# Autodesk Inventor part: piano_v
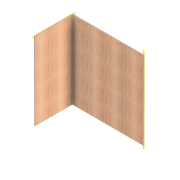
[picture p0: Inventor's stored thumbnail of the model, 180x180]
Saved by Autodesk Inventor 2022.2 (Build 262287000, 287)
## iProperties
Created: 2025-02
Part Number: piano_v
Material: Legno (betulla)
Document SubType Name: Modeling
Designer: 18907419
Density: 0.55 g/cm^3
Appearance: Betulla - Naturale lucidata
Author: 18907419
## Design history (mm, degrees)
node "Piano di lavoro1"
sketch "Schizzo1"
  geometry: L1 (0, -10)-(-20, 10) reference; L2 (-939.693, 10)-(-20, 10) reference; L3 (-939.693, -10)-(-939.693, 10) reference; L4 (-939.693, -10)-(0, -10) reference; L5 (-20, 990)-(0, 1010) reference; L6 (-939.693, 1010)-(0, 1010) reference; L7 (-939.693, 1010)-(-939.693, 990) reference; L8 (-20, 990)-(-939.693, 990) reference; L9 (0, 1010)-(-939.693, 1010); L10 (-939.693, 1010)-(-939.693, -10); L11 (-939.693, -10)-(0, -10); L12 (0, -10)-(0, 1010); L13 (-939.693, 1010)-(-929.693, 1010); L14 (-929.693, 1010)-(-929.693, -10); L15 (-929.693, -10)-(-939.693, -10); L16 (-939.693, -10)-(-939.693, 1010); 8 further points
  constraints: 16 end point, 1 point on line
  dimensions: "d2" = 10 distance of L14.end L15.end
extrude "Estrusione1" new body sketch "Schizzo1" distance "d0" = 10; taper "d1" = 0 deg
node "Piano di lavoro2"
sketch "Schizzo2"
  geometry: L1 (-1020, -10)-(-1020, 510) reference; L2 (0, 10)-(-1020, 10) reference; L3 (-1020, 510)-(0, 510); L4 (0, 510)-(0, 10); L5 (0, 10)-(-1020, 10); L6 (-1020, 10)-(-1020, 510); 1 further point
  constraints: 8 end point
extrude "Estrusione2" join sketch "Schizzo2" distance "d3" = 10; taper "d4" = 0 deg
node "Solido1"
node "Riferimento1"
node "Riferimento2"
node "Riferimento3"
